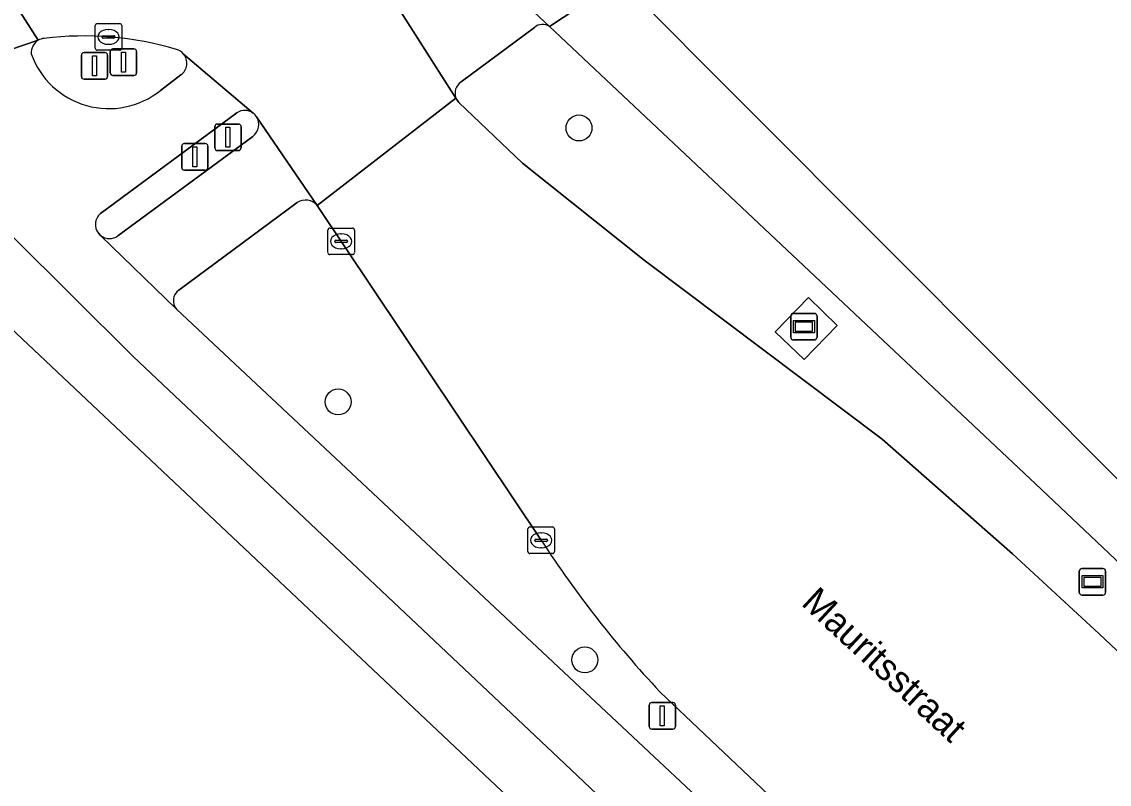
# Model space of a CAD drawing. Extents: x 160102 to 160934, y 382045 to 382923.
# Drawn here: x 160856.06 to 160897.03, y 382879.93 to 382908.64 of the extents above; entities that cross this region are included whole.
import ezdxf

# ---------------------------------------------------------------- set-up
doc = ezdxf.new("R2010")
doc.units = 0
for name, color, linetype in [('IMGEO_Berm_gesloten', 7, 'Continuous'), ('IMGEO_Berm_groen', 7, 'Continuous'), ('IMGEO_Boom', 7, 'Continuous'), ('IMGEO_Drukknoppaal', 7, 'Continuous'), ('IMGEO_Fietspad_gesloten', 7, 'Continuous'), ('IMGEO_Informatiebord', 7, 'Continuous'), ('IMGEO_Kolk', 7, 'Continuous'), ('IMGEO_Lichtmast', 7, 'Continuous'), ('IMGEO_Openbare_ruimte_label', 7, 'Continuous'), ('IMGEO_Pand', 7, 'Continuous'), ('IMGEO_Rijbaan_lokaal_gesloten', 7, 'Continuous'), ('IMGEO_Verkeerseiland_gesloten', 7, 'Continuous'), ('IMGEO_Verkeersregelinstallatiepaal', 7, 'Continuous'), ('IMGEO_Voetpad_gesloten', 7, 'Continuous'), ('IMGEO_Voetpad_open', 7, 'Continuous'), ('IMGEO_Wegwijzer', 7, 'Continuous')]:
    doc.layers.add(name, color=color, linetype=linetype)

msp = doc.modelspace()

# ---------------------------------------------------------------- linework, layer by layer
at = {"layer": 'IMGEO_Berm_gesloten'}
msp.add_lwpolyline([(160885.695, 382898.257), (160884.438, 382896.96), (160885.535, 382895.92), (160886.774, 382897.199)], close=True, dxfattribs=at)
at = {"layer": 'IMGEO_Berm_groen'}
for points in [[(160875.373, 382908.426), (160872.612, 382906.373)], [(160898.626, 382887.092), (160894.253, 382891.237), (160875.946, 382908.454)], [(160872.419, 382905.762), (160872.527, 382905.593), (160874.923, 382903.315), (160879.506, 382899.658), (160888.473, 382892.915), (160893.381, 382888.596), (160896.643, 382885.589), (160918.048, 382865.449)], [(160866.438, 382901.827), (160861.976, 382898.535)], [(160875.63, 382889.113), (160867.193, 382901.716)], [(160861.894, 382897.82), (160881.279, 382879.654), (160908.09, 382854.364)], [(160885.39, 382878.401), (160880.101, 382883.405)]]:
    msp.add_lwpolyline(points, dxfattribs=at)
msp.add_lwpolyline([(160885.535, 382895.92), (160884.438, 382896.96), (160885.695, 382898.257), (160886.774, 382897.199)], close=True, dxfattribs=at)
for centre, radius, start, end in [((160875.678, 382908.06), 0.476, 55.7511, 129.844), ((160872.891, 382905.949), 0.508, 123.3426, 201.5973), ((160866.756, 382901.366), 0.56, 38.7017, 124.5709), ((160862.26, 382898.14), 0.487, 125.7592, 221.156), ((160910.746, 382912.014), 41.924, 213.1104, 223.0318)]:
    msp.add_arc(centre, radius, start, end, dxfattribs=at)
at = {"layer": 'IMGEO_Boom'}
for centre in [(160877.054, 382904.638), (160867.981, 382894.322), (160877.271, 382884.608)]:
    msp.add_circle(centre, 0.489, dxfattribs=at)
at = {"layer": 'IMGEO_Drukknoppaal'}
for p, q in [((160862.088, 382903.149), (160862.088, 382903.949)), ((160862.088, 382903.949), (160862.088, 382903.149)), ((160862.188, 382904.049), (160862.978, 382904.049)), ((160862.978, 382904.049), (160862.188, 382904.049)), ((160863.078, 382903.949), (160863.078, 382903.149)), ((160863.078, 382903.149), (160863.078, 382903.949)), ((160862.978, 382903.049), (160862.188, 382903.049)), ((160862.188, 382903.049), (160862.978, 382903.049))]:
    msp.add_line(p, q, dxfattribs=at)
msp.add_lwpolyline([(160862.508, 382903.924), (160862.658, 382903.924), (160862.658, 382903.174), (160862.508, 382903.174), (160862.508, 382903.924)], dxfattribs=at)
for centre, start, end in [((160862.188, 382903.949), 90, 180), ((160862.188, 382903.949), 90, 180), ((160862.978, 382903.949), 0, 90), ((160862.978, 382903.949), 360, 90), ((160862.188, 382903.149), 180, 270), ((160862.188, 382903.149), 180, 270), ((160862.978, 382903.149), 270, 0), ((160862.978, 382903.149), 270, 0)]:
    msp.add_arc(centre, 0.1, start, end, dxfattribs=at)
at = {"layer": 'IMGEO_Fietspad_gesloten'}
for points in [[(160856.685, 382907.939), (160854.025, 382907.035)], [(160864.781, 382905.198), (160862.16, 382907.421)], [(160854.521, 382906.665), (160855.067, 382904.509), (160855.706, 382900.56), (160860.259, 382896.037), (160876.3, 382880.906), (160880.807, 382876.637), (160907.683, 382851.452)], [(160862.061, 382906.639), (160861.286, 382906.048)], [(160859.033, 382901.418), (160864.171, 382905.21)], [(160911, 382851.612), (160908.09, 382854.364), (160881.279, 382879.654), (160861.894, 382897.82), (160859.046, 382900.582), (160858.953, 382900.672)]]:
    msp.add_lwpolyline(points, dxfattribs=at)
for centre, radius, start, end in [((160856.968, 382907.472), 0.546, 121.2127, 184.946), ((160859.346, 382908.471), 3.104, 199.702, 308.672), ((160861.744, 382907.076), 0.54, 305.925, 39.6446), ((160864.467, 382904.762), 0.537, 54.2711, 123.475), ((160859.371, 382901.004), 0.534, 129.2847, 218.4734)]:
    msp.add_arc(centre, radius, start, end, dxfattribs=at)
at = {"layer": 'IMGEO_Informatiebord'}
for p, q in [((160885.03, 382896.756), (160885.03, 382897.556)), ((160885.03, 382897.556), (160885.03, 382896.756)), ((160885.13, 382897.656), (160885.92, 382897.656)), ((160885.92, 382897.656), (160885.13, 382897.656)), ((160886.02, 382897.556), (160886.02, 382896.756)), ((160886.02, 382896.756), (160886.02, 382897.556)), ((160885.92, 382896.656), (160885.13, 382896.656)), ((160885.13, 382896.656), (160885.92, 382896.656))]:
    msp.add_line(p, q, dxfattribs=at)
for points in [[(160885.131, 382897.388), (160885.919, 382897.388), (160885.919, 382896.924), (160885.131, 382896.924), (160885.131, 382897.388)], [(160885.196, 382897.323), (160885.196, 382896.989), (160885.854, 382896.989), (160885.854, 382897.323), (160885.196, 382897.323)]]:
    msp.add_lwpolyline(points, dxfattribs=at)
for centre, start, end in [((160885.13, 382897.556), 90, 180), ((160885.13, 382897.556), 90, 180), ((160885.92, 382897.556), 0, 90), ((160885.92, 382897.556), 360, 90), ((160885.13, 382896.756), 180, 270), ((160885.13, 382896.756), 180, 270), ((160885.92, 382896.756), 270, 0), ((160885.92, 382896.756), 270, 0)]:
    msp.add_arc(centre, 0.1, start, end, dxfattribs=at)
at = {"layer": 'IMGEO_Kolk'}
for p, q in [((160858.832, 382907.642), (160858.832, 382908.494)), ((160858.907, 382908.568), (160859.759, 382908.568)), ((160859.833, 382908.494), (160859.833, 382907.642)), ((160859.091, 382908.062), (160859.091, 382908.074)), ((160859.529, 382908.025), (160859.131, 382908.025)), ((160859.134, 382908.111), (160859.532, 382908.111)), ((160859.32, 382908.348), (160859.345, 382908.348)), ((160859.575, 382908.074), (160859.575, 382908.062)), ((160859.343, 382907.788), (160859.318, 382907.788)), ((160859.759, 382907.568), (160858.907, 382907.568)), ((160867.595, 382899.943), (160867.595, 382900.795)), ((160867.67, 382900.869), (160868.522, 382900.869)), ((160868.083, 382900.649), (160868.108, 382900.649)), ((160868.596, 382900.795), (160868.596, 382899.943)), ((160867.854, 382900.363), (160867.854, 382900.375)), ((160868.292, 382900.326), (160867.894, 382900.326)), ((160867.897, 382900.412), (160868.295, 382900.412)), ((160868.338, 382900.375), (160868.338, 382900.363)), ((160868.522, 382899.869), (160867.67, 382899.869)), ((160868.106, 382900.089), (160868.081, 382900.089)), ((160875.204, 382889.613), (160876.056, 382889.613)), ((160875.129, 382888.687), (160875.129, 382889.539)), ((160875.617, 382889.393), (160875.642, 382889.393)), ((160876.13, 382889.539), (160876.13, 382888.687)), ((160875.388, 382889.107), (160875.388, 382889.119)), ((160875.826, 382889.07), (160875.428, 382889.07)), ((160875.431, 382889.156), (160875.829, 382889.156)), ((160875.64, 382888.833), (160875.615, 382888.833)), ((160875.872, 382889.119), (160875.872, 382889.107)), ((160876.056, 382888.613), (160875.204, 382888.613))]:
    msp.add_line(p, q, dxfattribs=at)
for points in [[(160858.832, 382907.642), (160858.832, 382908.494)], [(160858.907, 382908.568), (160859.759, 382908.568)], [(160859.833, 382908.494), (160859.833, 382907.642)], [(160859.759, 382907.568), (160858.907, 382907.568)], [(160867.595, 382899.943), (160867.595, 382900.795)], [(160867.67, 382900.869), (160868.522, 382900.869)], [(160868.596, 382900.795), (160868.596, 382899.943)], [(160868.522, 382899.869), (160867.67, 382899.869)], [(160875.204, 382889.613), (160876.056, 382889.613)], [(160875.129, 382888.687), (160875.129, 382889.539)], [(160876.13, 382889.539), (160876.13, 382888.687)], [(160876.056, 382888.613), (160875.204, 382888.613)]]:
    msp.add_lwpolyline(points, dxfattribs=at)
for centre, radius, start, end in [((160858.909, 382908.492), 0.0765, 91.552, 178.448), ((160858.909, 382908.492), 0.0765, 91.552, 178.448), ((160859.757, 382908.492), 0.0765, 1.552, 88.448), ((160859.757, 382908.492), 0.0765, 1.552, 88.448), ((160859.131, 382908.071), 0.0403, 85.8775, 175.7526), ((160859.128, 382908.061), 0.0366, 178.938, 274.7102), ((160859.532, 382908.068), 0.043, 264.8664, 352.4533), ((160859.536, 382908.073), 0.0386, 1.7309, 96.639), ((160858.909, 382907.644), 0.0765, 181.552, 268.448), ((160858.909, 382907.644), 0.0765, 181.552, 268.448), ((160859.757, 382907.644), 0.0765, 271.552, 358.448), ((160859.757, 382907.644), 0.0765, 271.552, 358.448), ((160867.672, 382900.793), 0.0765, 91.552, 178.448), ((160867.672, 382900.793), 0.0765, 91.552, 178.448), ((160868.52, 382900.793), 0.0765, 1.552, 88.448), ((160868.52, 382900.793), 0.0765, 1.552, 88.448), ((160867.894, 382900.372), 0.0403, 85.8775, 175.7526), ((160867.891, 382900.362), 0.0366, 178.938, 274.7102), ((160868.295, 382900.369), 0.043, 264.8664, 352.4533), ((160868.299, 382900.374), 0.0386, 1.7309, 96.639), ((160867.672, 382899.945), 0.0765, 181.552, 268.448), ((160867.672, 382899.945), 0.0765, 181.552, 268.448), ((160868.52, 382899.945), 0.0765, 271.552, 358.448), ((160868.52, 382899.945), 0.0765, 271.552, 358.448), ((160875.206, 382889.537), 0.0765, 91.552, 178.448), ((160875.206, 382889.537), 0.0765, 91.552, 178.448), ((160876.054, 382889.537), 0.0765, 1.552, 88.448), ((160876.054, 382889.537), 0.0765, 1.552, 88.448), ((160875.428, 382889.116), 0.0403, 85.8775, 175.7526), ((160875.425, 382889.106), 0.0366, 178.938, 274.7102), ((160875.829, 382889.113), 0.043, 264.8664, 352.4533), ((160875.833, 382889.118), 0.0386, 1.7309, 96.639), ((160875.206, 382888.689), 0.0765, 181.552, 268.448), ((160875.206, 382888.689), 0.0765, 181.552, 268.448), ((160876.054, 382888.689), 0.0765, 271.552, 358.448), ((160876.054, 382888.689), 0.0765, 271.552, 358.448)]:
    msp.add_arc(centre, radius, start, end, dxfattribs=at)
for centre, major_axis, ratio, start_param, end_param in [((160859.319, 382908.068), (-0.387, 0.002), 0.722429, 4.712389, 7.853982), ((160859.344, 382908.068), (-0.39, 0.002), 0.717154, 1.570796, 4.712389), ((160868.082, 382900.369), (-0.387, 0.002), 0.722429, 4.712389, 7.853982), ((160868.107, 382900.369), (-0.39, 0.002), 0.717154, 1.570796, 4.712389), ((160875.616, 382889.113), (-0.387, 0.002), 0.722429, 4.712389, 7.853982), ((160875.641, 382889.113), (-0.39, 0.002), 0.717154, 1.570796, 4.712389)]:
    msp.add_ellipse(centre, major_axis=major_axis, ratio=ratio, start_param=start_param, end_param=end_param, dxfattribs=at)
at = {"layer": 'IMGEO_Lichtmast'}
for p, q in [((160858.31, 382906.577), (160858.31, 382907.377)), ((160858.31, 382907.377), (160858.31, 382906.577)), ((160858.41, 382907.477), (160859.2, 382907.477)), ((160859.2, 382907.477), (160858.41, 382907.477)), ((160859.3, 382907.377), (160859.3, 382906.577)), ((160859.3, 382906.577), (160859.3, 382907.377)), ((160859.2, 382906.477), (160858.41, 382906.477)), ((160858.41, 382906.477), (160859.2, 382906.477)), ((160879.697, 382882.102), (160879.697, 382882.902)), ((160879.697, 382882.902), (160879.697, 382882.102)), ((160879.797, 382883.002), (160880.587, 382883.002)), ((160880.587, 382883.002), (160879.797, 382883.002)), ((160880.687, 382882.902), (160880.687, 382882.102)), ((160880.687, 382882.102), (160880.687, 382882.902)), ((160880.587, 382882.002), (160879.797, 382882.002)), ((160879.797, 382882.002), (160880.587, 382882.002))]:
    msp.add_line(p, q, dxfattribs=at)
for points in [[(160858.73, 382907.352), (160858.88, 382907.352), (160858.88, 382906.602), (160858.73, 382906.602), (160858.73, 382907.352)], [(160880.117, 382882.877), (160880.267, 382882.877), (160880.267, 382882.127), (160880.117, 382882.127), (160880.117, 382882.877)]]:
    msp.add_lwpolyline(points, dxfattribs=at)
for centre, start, end in [((160858.41, 382907.377), 90, 180), ((160858.41, 382907.377), 90, 180), ((160859.2, 382907.377), 0, 90), ((160859.2, 382907.377), 360, 90), ((160858.41, 382906.577), 180, 270), ((160858.41, 382906.577), 180, 270), ((160859.2, 382906.577), 270, 0), ((160859.2, 382906.577), 270, 0), ((160879.797, 382882.902), 90, 180), ((160879.797, 382882.902), 90, 180), ((160880.587, 382882.902), 0, 90), ((160880.587, 382882.902), 360, 90), ((160879.797, 382882.102), 180, 270), ((160879.797, 382882.102), 180, 270), ((160880.587, 382882.102), 270, 0), ((160880.587, 382882.102), 270, 0)]:
    msp.add_arc(centre, 0.1, start, end, dxfattribs=at)
at = {"layer": 'IMGEO_Pand'}
msp.add_lwpolyline([(160840.366, 382848.876), (160858.731, 382865.029), (160862.028, 382861.283), (160864.631, 382863.667), (160866.424, 382865.309), (160866.606, 382865.137), (160874.688, 382872.462), (160873.916, 382873.267), (160874.9, 382874.311), (160873.01, 382876.092), (160875.468, 382878.428), (160854.082, 382898.574)], dxfattribs=at)
at = {"layer": 'IMGEO_Rijbaan_lokaal_gesloten'}
for points in [[(160873.085, 382911.142), (160875.946, 382908.454), (160878.596, 382910.215), (160865.751, 382923.099), (160851.95, 382915.343)], [(160854.025, 382907.035), (160856.685, 382907.939), (160851.95, 382915.343), (160847.873, 382913.052)], [(160851.95, 382915.343), (160856.685, 382907.939)], [(160864.911, 382905.064), (160867.193, 382901.716), (160872.419, 382905.762), (160870.255, 382909.145), (160868.574, 382912.144), (160868.181, 382913.612)], [(160862.16, 382907.421), (160864.781, 382905.198)], [(160896.643, 382885.589), (160893.381, 382888.596), (160888.473, 382892.915), (160879.506, 382899.658), (160874.923, 382903.315), (160872.527, 382905.593), (160872.419, 382905.762), (160867.193, 382901.716), (160875.63, 382889.113)], [(160880.101, 382883.405), (160885.39, 382878.401), (160894.512, 382869.771), (160909.375, 382855.754), (160918.048, 382865.449), (160896.643, 382885.589)]]:
    msp.add_lwpolyline(points, dxfattribs=at)
msp.add_lwpolyline([(160920.419, 382868.265), (160898.025, 382890.727), (160878.596, 382910.215), (160875.946, 382908.454), (160894.253, 382891.237), (160898.626, 382887.092), (160919.573, 382867.32)], close=True, dxfattribs=at)
for centre, radius, start, end in [((160856.96, 382907.486), 0.53, 96.208, 121.2915), ((160858.395, 382895.807), 12.297, 73.4595, 96.9696), ((160861.746, 382907.081), 0.536, 39.4511, 73.7719), ((160864.48, 382904.776), 0.518, 33.7454, 54.5185), ((160910.746, 382912.014), 41.924, 213.1104, 223.0318)]:
    msp.add_arc(centre, radius, start, end, dxfattribs=at)
at = {"layer": 'IMGEO_Verkeerseiland_gesloten'}
for points in [[(160861.286, 382906.048), (160862.061, 382906.639)], [(160864.171, 382905.21), (160859.033, 382901.418)], [(160859.684, 382900.573), (160864.77, 382904.321)], [(160858.953, 382900.672), (160859.046, 382900.582)]]:
    msp.add_lwpolyline(points, dxfattribs=at)
for centre, radius, start, end in [((160856.96, 382907.486), 0.53, 96.208, 121.2915), ((160858.395, 382895.807), 12.297, 73.4595, 96.9696), ((160856.968, 382907.472), 0.546, 121.2127, 184.946), ((160859.346, 382908.471), 3.104, 199.702, 308.672), ((160861.746, 382907.081), 0.536, 39.4511, 73.7719), ((160861.744, 382907.076), 0.54, 305.925, 39.6446), ((160864.467, 382904.762), 0.537, 54.2711, 123.475), ((160864.48, 382904.776), 0.518, 33.7454, 54.5185), ((160864.432, 382904.77), 0.562, 307.0012, 31.5082), ((160859.371, 382901.004), 0.534, 129.2847, 218.4734), ((160859.371, 382901.002), 0.531, 232.2657, 306.1179)]:
    msp.add_arc(centre, radius, start, end, dxfattribs=at)
at = {"layer": 'IMGEO_Verkeersregelinstallatiepaal'}
for p, q in [((160859.5, 382907.613), (160860.29, 382907.613)), ((160860.29, 382907.613), (160859.5, 382907.613)), ((160859.4, 382906.713), (160859.4, 382907.513)), ((160859.4, 382907.513), (160859.4, 382906.713)), ((160860.39, 382907.513), (160860.39, 382906.713)), ((160860.39, 382906.713), (160860.39, 382907.513)), ((160860.29, 382906.613), (160859.5, 382906.613)), ((160859.5, 382906.613), (160860.29, 382906.613)), ((160863.436, 382904.788), (160864.226, 382904.788)), ((160864.226, 382904.788), (160863.436, 382904.788)), ((160863.336, 382903.888), (160863.336, 382904.688)), ((160863.336, 382904.688), (160863.336, 382903.888)), ((160864.326, 382904.688), (160864.326, 382903.888)), ((160864.326, 382903.888), (160864.326, 382904.688)), ((160864.226, 382903.788), (160863.436, 382903.788)), ((160863.436, 382903.788), (160864.226, 382903.788))]:
    msp.add_line(p, q, dxfattribs=at)
for points in [[(160859.82, 382907.488), (160859.97, 382907.488), (160859.97, 382906.738), (160859.82, 382906.738), (160859.82, 382907.488)], [(160863.756, 382904.663), (160863.906, 382904.663), (160863.906, 382903.913), (160863.756, 382903.913), (160863.756, 382904.663)]]:
    msp.add_lwpolyline(points, dxfattribs=at)
for centre, start, end in [((160859.5, 382907.513), 90, 180), ((160859.5, 382907.513), 90, 180), ((160860.29, 382907.513), 0, 90), ((160860.29, 382907.513), 360, 90), ((160859.5, 382906.713), 180, 270), ((160859.5, 382906.713), 180, 270), ((160860.29, 382906.713), 270, 0), ((160860.29, 382906.713), 270, 0), ((160863.436, 382904.688), 90, 180), ((160863.436, 382904.688), 90, 180), ((160864.226, 382904.688), 0, 90), ((160864.226, 382904.688), 360, 90), ((160863.436, 382903.888), 180, 270), ((160863.436, 382903.888), 180, 270), ((160864.226, 382903.888), 270, 0), ((160864.226, 382903.888), 270, 0)]:
    msp.add_arc(centre, 0.1, start, end, dxfattribs=at)
at = {"layer": 'IMGEO_Voetpad_gesloten'}
for points in [[(160875.946, 382908.454), (160873.085, 382911.142)], [(160870.255, 382909.145), (160872.419, 382905.762)], [(160872.612, 382906.373), (160875.373, 382908.426)], [(160867.193, 382901.716), (160864.911, 382905.064)], [(160864.77, 382904.321), (160859.684, 382900.573)], [(160861.976, 382898.535), (160866.438, 382901.827)], [(160859.046, 382900.582), (160861.894, 382897.82)]]:
    msp.add_lwpolyline(points, dxfattribs=at)
for centre, radius, start, end in [((160875.678, 382908.06), 0.476, 55.7511, 129.844), ((160872.891, 382905.949), 0.508, 123.3426, 201.5973), ((160864.432, 382904.77), 0.562, 307.0012, 31.5082), ((160866.756, 382901.366), 0.56, 38.7017, 124.5709), ((160859.371, 382901.002), 0.531, 232.2657, 306.1179), ((160862.26, 382898.14), 0.487, 125.7592, 221.156)]:
    msp.add_arc(centre, radius, start, end, dxfattribs=at)
at = {"layer": 'IMGEO_Voetpad_open'}
for points in [[(160851.435, 382901.477), (160851.784, 382900.791), (160852.299, 382899.776), (160853.109, 382897.965), (160854.082, 382898.574), (160875.468, 382878.428), (160906.401, 382849.614), (160908.483, 382847.486), (160909.809, 382846.282)], [(160880.807, 382876.637), (160876.3, 382880.906), (160860.259, 382896.037), (160855.706, 382900.56)]]:
    msp.add_lwpolyline(points, dxfattribs=at)
at = {"layer": 'IMGEO_Wegwijzer'}
for p, q in [((160895.899, 382887.149), (160895.899, 382887.949)), ((160895.899, 382887.949), (160895.899, 382887.149)), ((160895.999, 382888.049), (160896.789, 382888.049)), ((160896.789, 382888.049), (160895.999, 382888.049)), ((160896.889, 382887.949), (160896.889, 382887.149)), ((160896.889, 382887.149), (160896.889, 382887.949)), ((160896.789, 382887.049), (160895.999, 382887.049)), ((160895.999, 382887.049), (160896.789, 382887.049))]:
    msp.add_line(p, q, dxfattribs=at)
for points in [[(160896, 382887.781), (160896.788, 382887.781), (160896.788, 382887.317), (160896, 382887.317), (160896, 382887.781)], [(160896.065, 382887.716), (160896.065, 382887.382), (160896.723, 382887.382), (160896.723, 382887.716), (160896.065, 382887.716)]]:
    msp.add_lwpolyline(points, dxfattribs=at)
for centre, start, end in [((160895.999, 382887.949), 90, 180), ((160895.999, 382887.949), 90, 180), ((160896.789, 382887.949), 0, 90), ((160896.789, 382887.949), 360, 90), ((160895.999, 382887.149), 180, 270), ((160895.999, 382887.149), 180, 270), ((160896.789, 382887.149), 270, 0), ((160896.789, 382887.149), 270, 0)]:
    msp.add_arc(centre, 0.1, start, end, dxfattribs=at)

# ---------------------------------------------------------------- texts
at = {"layer": 'IMGEO_Openbare_ruimte_label'}
msp.add_text('Mauritsstraat', height=1, rotation=317.2291, dxfattribs=at).set_placement((160885.386, 382886.697))

doc.saveas('drawing.dxf')
